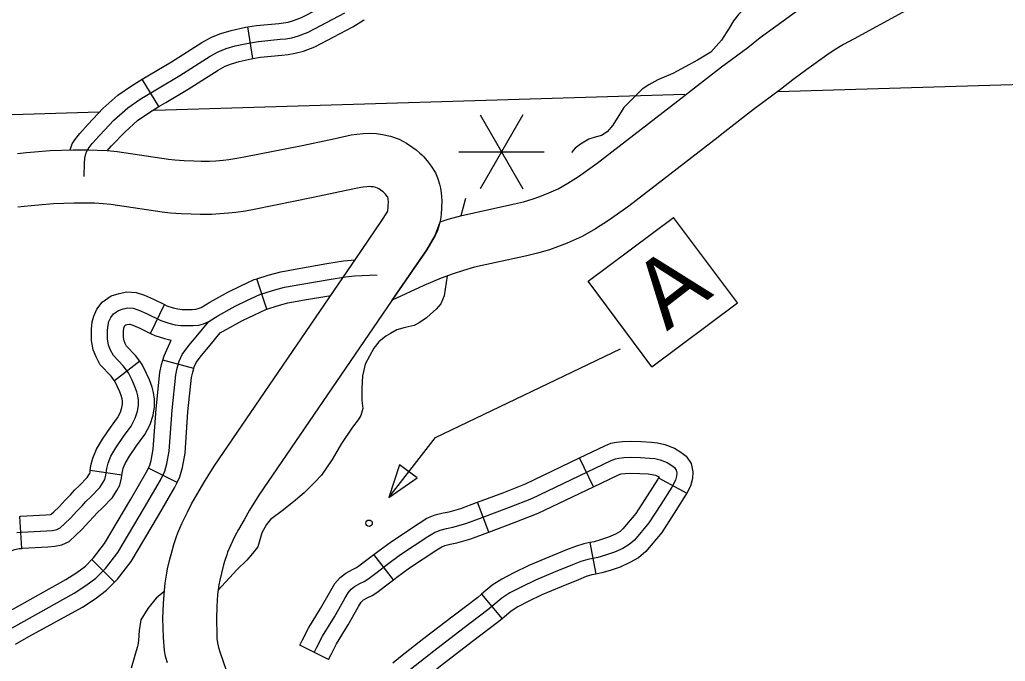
# Model space of a CAD drawing. Extents: x -3711 to 825, y -151 to 1050.
# Drawn here: x -2828.2 to -2776.5, y 291.3 to 325 of the extents above; entities that cross this region are included whole.
import ezdxf

# ---------------------------------------------------------------- set-up
doc = ezdxf.new("R2010")
doc.units = 0
for name, color, linetype in [('Level 10', 7, 'Continuous'), ('Level 32', 7, 'Continuous'), ('Level 35', 7, 'Continuous'), ('Level 48', 7, 'Continuous'), ('Level 5', 7, 'Continuous'), ('Level 57', 7, 'Continuous')]:
    doc.layers.add(name, color=color, linetype=linetype)

msp = doc.modelspace()

# ---------------------------------------------------------------- linework, layer by layer
at = {"layer": 'Level 10'}
for points in [[(-2781.289, 325.669), (-2784.41, 323.971), (-2784.959, 323.669), (-2785.452, 323.371), (-2785.849, 323.106), (-2786.891, 322.363), (-2787.635, 321.823), (-2788.274, 321.3), (-2789.685, 320.256), (-2791.36, 318.961), (-2791.549, 318.808), (-2796.241, 315.189), (-2797.309, 314.427), (-2797.995, 313.986), (-2798.695, 313.596), (-2799.472, 313.245), (-2799.985, 313.04), (-2800.41, 312.894), (-2801.033, 312.71), (-2801.598, 312.569), (-2804.337, 311.973), (-2804.917, 311.81), (-2805.469, 311.633), (-2806.101, 311.405), (-2807.006, 311.022), (-2808.664, 310.249)], [(-2808.664, 310.249), (-2806.854, 312.899), (-2806.413, 313.636), (-2806.15, 314.357), (-2805.725, 314.494), (-2805.014, 314.694), (-2802.236, 315.298), (-2801.77, 315.414), (-2801.262, 315.564), (-2800.962, 315.667), (-2800.569, 315.824), (-2799.956, 316.101), (-2799.436, 316.391), (-2798.88, 316.748), (-2797.911, 317.44), (-2793.288, 321.005), (-2793.101, 321.157), (-2791.376, 322.491), (-2789.996, 323.512), (-2789.347, 324.044), (-2788.528, 324.638), (-2787.441, 325.413)], [(-2828.337, 317.95), (-2827.872, 318.002), (-2827.449, 318.028), (-2826.627, 318.101), (-2825.41, 318.146), (-2824.849, 318.146), (-2824.588, 318.146), (-2824.163, 318.13), (-2823.634, 318.097), (-2823.108, 318.051), (-2820.405, 317.646), (-2820.085, 317.614), (-2819.587, 317.587), (-2819.083, 317.559), (-2818.695, 317.543), (-2818.251, 317.546), (-2817.922, 317.571), (-2817.533, 317.6), (-2817.237, 317.634), (-2816.831, 317.694), (-2816.447, 317.764), (-2813.387, 318.374), (-2811.668, 318.743), (-2810.816, 318.923), (-2810.531, 318.967), (-2810.197, 318.999), (-2809.862, 319.017), (-2809.498, 318.997), (-2809.167, 318.95), (-2808.747, 318.856), (-2808.308, 318.699), (-2807.923, 318.496), (-2807.59, 318.268), (-2807.413, 318.133), (-2807.209, 317.967), (-2807.114, 317.873), (-2807.019, 317.787), (-2806.828, 317.57), (-2806.615, 317.277), (-2806.391, 316.928), (-2806.287, 316.672), (-2806.228, 316.506), (-2806.181, 316.331), (-2806.135, 316.129), (-2806.092, 315.881), (-2806.064, 315.469), (-2806.072, 315.089), (-2806.089, 314.768), (-2806.133, 314.475), (-2806.194, 314.203), (-2806.288, 313.913), (-2806.413, 313.636), (-2806.529, 313.427), (-2806.854, 312.899)], [(-2809.205, 314.422), (-2808.95, 314.839), (-2808.919, 314.894), (-2808.906, 314.924), (-2808.9, 314.941), (-2808.889, 314.989), (-2808.88, 315.052), (-2808.872, 315.195), (-2808.868, 315.403), (-2808.877, 315.542), (-2808.884, 315.579), (-2808.899, 315.649), (-2808.93, 315.696), (-2809.016, 315.814), (-2809.044, 315.84), (-2809.087, 315.883), (-2809.145, 315.93), (-2809.232, 315.996), (-2809.374, 316.093), (-2809.44, 316.128), (-2809.526, 316.159), (-2809.67, 316.191), (-2809.775, 316.206), (-2809.863, 316.211), (-2809.989, 316.204), (-2810.183, 316.186), (-2810.311, 316.166), (-2811.085, 316.003), (-2812.819, 315.63), (-2815.921, 315.012), (-2816.376, 314.929), (-2816.87, 314.856), (-2817.265, 314.81), (-2817.714, 314.776), (-2818.139, 314.745), (-2818.743, 314.741), (-2819.218, 314.76), (-2819.741, 314.789), (-2820.299, 314.819), (-2820.751, 314.864), (-2823.438, 315.267), (-2823.844, 315.302), (-2824.303, 315.332), (-2824.64, 315.344), (-2824.849, 315.344), (-2825.358, 315.344), (-2826.452, 315.303), (-2827.239, 315.234), (-2827.63, 315.209), (-2827.994, 315.169), (-2828.332, 315.123)], [(-2820.465, 291.205), (-2820.545, 291.497), (-2820.583, 291.654), (-2820.62, 291.863), (-2820.646, 292.086), (-2820.662, 292.296), (-2820.679, 292.549), (-2820.703, 293.545), (-2820.672, 294.317), (-2820.628, 295.009), (-2820.592, 295.394), (-2820.526, 295.805), (-2820.457, 296.144), (-2820.358, 296.579), (-2820.224, 297.093), (-2820.129, 297.422), (-2820.006, 297.79), (-2819.921, 298.03), (-2819.816, 298.281), (-2819.698, 298.565), (-2819.422, 299.124), (-2819.197, 299.558), (-2818.874, 300.122), (-2818.561, 300.664), (-2818.012, 301.539), (-2810.765, 312.144), (-2810.617, 312.362), (-2809.205, 314.422)], [(-2806.854, 312.899), (-2808.302, 310.783), (-2808.45, 310.566), (-2815.668, 300.003), (-2816.16, 299.218), (-2816.445, 298.725), (-2816.736, 298.217), (-2816.921, 297.859), (-2817.146, 297.405), (-2817.229, 297.206), (-2817.306, 297.02), (-2817.357, 296.876), (-2817.453, 296.588), (-2817.522, 296.351), (-2817.635, 295.917), (-2817.718, 295.55), (-2817.769, 295.302), (-2817.811, 295.042), (-2817.834, 294.789), (-2817.874, 294.173), (-2817.899, 293.524), (-2817.879, 292.672), (-2817.867, 292.495), (-2817.857, 292.359), (-2817.847, 292.273), (-2817.838, 292.225), (-2817.83, 292.192), (-2817.782, 292.018), (-2817.708, 291.794), (-2817.211, 290.322)]]:
    msp.add_lwpolyline(points, dxfattribs=at)
at = {"layer": 'Level 32'}
for p, q in [((-2815.977, 322.934), (-2816.24, 324.595)), ((-2820.914, 320.41), (-2821.787, 321.846)), ((-2815.254, 309.772), (-2815.774, 311.371)), ((-2821.356, 308.507), (-2820.618, 310.017)), ((-2821.921, 307.046), (-2823.252, 306.019)), ((-2819.089, 306.653), (-2820.708, 307.106)), ((-2798.1, 300.451), (-2798.826, 301.968)), ((-2822.855, 301.062), (-2824.519, 301.3)), ((-2819.964, 300.67), (-2821.468, 301.421)), ((-2794.683, 300.913), (-2793.198, 300.125)), ((-2803.597, 298.075), (-2804.183, 299.651)), ((-2828.113, 297.22), (-2828.225, 298.898)), ((-2798.288, 297.52), (-2797.965, 295.87)), ((-2823.25, 295.442), (-2824.439, 296.631)), ((-2808.604, 295.57), (-2809.626, 296.905)), ((-2803.969, 294.817), (-2802.896, 293.523)), ((-2812.008, 291.384), (-2813.512, 292.135))]:
    msp.add_line(p, q, dxfattribs=at)
for points in [[(-2816.24, 324.595), (-2815.795, 324.665), (-2814.625, 324.779), (-2814.366, 324.804), (-2814.129, 324.847), (-2813.844, 324.924), (-2813.427, 325.086), (-2811.566, 326.058), (-2811.079, 326.353), (-2811.076, 326.355)], [(-2824.849, 316.745), (-2824.828, 317.443), (-2824.799, 317.705), (-2824.76, 317.937), (-2824.709, 318.072), (-2824.634, 318.189), (-2824.425, 318.468), (-2824.02, 318.915), (-2823.28, 319.697), (-2822.555, 320.339), (-2821.897, 320.795), (-2820.987, 321.349), (-2819.813, 322.038), (-2818.228, 323.049), (-2817.796, 323.286), (-2817.377, 323.454), (-2816.917, 323.594), (-2816.219, 323.747), (-2815.688, 323.831), (-2814.544, 323.943), (-2814.251, 323.971), (-2813.944, 324.026), (-2813.581, 324.124), (-2813.079, 324.32), (-2811.153, 325.325)], [(-2821.787, 321.846), (-2821.418, 322.07), (-2820.252, 322.755), (-2818.657, 323.772), (-2818.156, 324.048), (-2817.656, 324.248), (-2817.129, 324.407), (-2816.375, 324.574), (-2816.24, 324.595)], [(-2815.977, 322.934), (-2815.582, 322.997), (-2814.463, 323.106), (-2814.136, 323.137), (-2813.759, 323.206), (-2813.319, 323.324), (-2812.731, 323.553), (-2810.74, 324.592), (-2810.166, 324.94), (-2810.122, 324.971)], [(-2820.914, 320.41), (-2820.556, 320.627), (-2819.374, 321.321), (-2817.8, 322.325), (-2817.436, 322.525), (-2817.098, 322.66), (-2816.704, 322.78), (-2816.063, 322.921), (-2815.977, 322.934)], [(-2825.582, 318.14), (-2825.464, 318.451), (-2825.325, 318.668), (-2825.074, 319.003), (-2824.637, 319.486), (-2823.865, 320.302), (-2823.075, 321.002), (-2822.355, 321.501), (-2821.787, 321.846)], [(-2823.627, 318.096), (-2823.403, 318.344), (-2822.695, 319.092), (-2822.035, 319.677), (-2821.439, 320.09), (-2820.914, 320.41)], [(-2815.774, 311.371), (-2815.183, 311.563), (-2814.513, 311.744), (-2813.56, 311.917), (-2812.103, 312.169), (-2811.227, 312.306), (-2810.61, 312.37)], [(-2828.377, 298.045), (-2828.127, 298.062), (-2826.797, 298.145), (-2826.498, 298.162), (-2826.282, 298.212), (-2826.099, 298.295), (-2825.85, 298.528), (-2825.55, 298.81), (-2825.218, 299.177), (-2824.952, 299.459), (-2824.752, 299.676), (-2824.486, 299.925), (-2824.021, 300.408), (-2823.838, 300.691), (-2823.755, 300.84), (-2823.705, 301.057), (-2823.655, 301.406), (-2823.588, 301.689), (-2823.439, 302.055), (-2823.173, 302.504), (-2822.774, 303.087), (-2822.375, 303.636), (-2822.159, 304.052), (-2822.042, 304.418), (-2821.992, 304.717), (-2821.992, 305), (-2822.026, 305.233), (-2822.075, 305.433), (-2822.192, 305.749), (-2822.325, 306.048), (-2822.508, 306.431), (-2822.79, 306.797), (-2823.306, 307.346), (-2823.455, 307.629), (-2823.555, 307.878), (-2823.622, 308.211), (-2823.622, 308.444), (-2823.622, 308.677), (-2823.588, 308.943), (-2823.539, 309.126), (-2823.439, 309.343), (-2823.306, 309.526), (-2823.04, 309.709), (-2822.79, 309.792), (-2822.541, 309.842), (-2822.275, 309.825), (-2821.976, 309.725), (-2821.56, 309.542), (-2820.812, 309.176), (-2820.396, 309.043), (-2820.064, 308.96), (-2819.764, 308.927), (-2819.449, 308.91), (-2819.116, 308.91), (-2818.817, 308.943), (-2818.567, 309.01), (-2818.301, 309.126), (-2817.819, 309.426), (-2816.905, 309.925), (-2816.256, 310.241), (-2815.608, 310.541), (-2814.943, 310.757), (-2814.328, 310.923), (-2813.413, 311.09), (-2811.967, 311.339), (-2811.119, 311.472), (-2810.637, 311.522), (-2809.459, 311.573)], [(-2820.618, 310.017), (-2820.497, 309.958), (-2820.166, 309.852), (-2819.915, 309.789), (-2819.696, 309.765), (-2819.426, 309.751), (-2819.163, 309.751), (-2818.972, 309.772), (-2818.846, 309.806), (-2818.694, 309.872), (-2818.243, 310.152), (-2817.291, 310.672), (-2816.617, 311.001), (-2815.915, 311.325), (-2815.774, 311.371)], [(-2823.252, 306.019), (-2823.431, 306.251), (-2823.996, 306.853), (-2824.219, 307.275), (-2824.364, 307.638), (-2824.462, 308.128), (-2824.462, 308.444), (-2824.462, 308.729), (-2824.415, 309.107), (-2824.331, 309.415), (-2824.167, 309.77), (-2823.901, 310.136), (-2823.418, 310.468), (-2823.007, 310.606), (-2822.598, 310.688), (-2822.113, 310.657), (-2821.673, 310.51), (-2821.206, 310.305), (-2820.618, 310.017)], [(-2815.254, 309.772), (-2814.703, 309.951), (-2814.142, 310.103), (-2813.267, 310.262), (-2811.889, 310.5)], [(-2817.699, 308.534), (-2816.519, 309.178), (-2815.896, 309.482), (-2815.301, 309.757), (-2815.254, 309.772)], [(-2830.035, 292.254), (-2828.148, 293.318), (-2825.363, 294.861), (-2824.749, 295.266), (-2824.225, 295.655), (-2823.716, 296.165), (-2823.072, 297.004), (-2821.664, 299.372), (-2820.841, 300.795), (-2820.601, 301.275), (-2820.496, 301.65), (-2820.377, 302.324), (-2820.227, 304.467), (-2820.032, 306.325), (-2819.957, 306.67), (-2819.852, 307.044), (-2819.688, 307.404), (-2819.343, 307.869), (-2818.864, 308.423), (-2818.301, 309.126)], [(-2821.921, 307.046), (-2822.15, 307.343), (-2822.616, 307.839), (-2822.691, 307.982), (-2822.746, 308.119), (-2822.781, 308.294), (-2822.781, 308.444), (-2822.781, 308.625), (-2822.762, 308.78), (-2822.746, 308.838), (-2822.71, 308.915), (-2822.661, 308.949), (-2822.574, 308.978), (-2822.484, 308.996), (-2822.437, 308.993), (-2822.279, 308.94), (-2821.914, 308.78), (-2821.356, 308.507)], [(-2821.356, 308.507), (-2821.126, 308.394), (-2820.627, 308.234), (-2820.273, 308.146)], [(-2819.089, 306.653), (-2819.061, 306.754), (-2818.96, 306.974), (-2818.687, 307.343), (-2818.218, 307.885), (-2817.699, 308.534)], [(-2820.708, 307.106), (-2820.644, 307.334), (-2820.273, 308.146)], [(-2822.855, 301.062), (-2822.828, 301.25), (-2822.785, 301.432), (-2822.684, 301.68), (-2822.464, 302.052), (-2822.087, 302.602), (-2821.658, 303.192), (-2821.379, 303.728), (-2821.223, 304.22), (-2821.152, 304.648), (-2821.152, 305.06), (-2821.2, 305.395), (-2821.271, 305.68), (-2821.412, 306.065), (-2821.561, 306.4), (-2821.788, 306.874), (-2821.921, 307.046)], [(-2821.468, 301.421), (-2821.389, 301.579), (-2821.317, 301.837), (-2821.212, 302.427), (-2821.064, 304.54), (-2820.863, 306.459), (-2820.773, 306.872), (-2820.708, 307.106)], [(-2819.964, 300.67), (-2819.813, 300.971), (-2819.676, 301.462), (-2819.541, 302.221), (-2819.389, 304.394), (-2819.201, 306.192), (-2819.141, 306.467), (-2819.089, 306.653)], [(-2824.519, 301.3), (-2824.482, 301.562), (-2824.392, 301.946), (-2824.194, 302.43), (-2823.882, 302.956), (-2823.461, 303.571), (-2823.092, 304.079), (-2822.938, 304.375), (-2822.862, 304.615), (-2822.833, 304.787), (-2822.833, 304.94), (-2822.852, 305.071), (-2822.88, 305.185), (-2822.971, 305.433), (-2823.088, 305.696), (-2823.228, 305.988), (-2823.252, 306.019)], [(-2798.826, 301.968), (-2797.504, 302.6), (-2797.189, 302.733), (-2796.887, 302.793), (-2796.567, 302.821), (-2796.177, 302.847), (-2795.589, 302.837), (-2795.057, 302.799), (-2794.736, 302.757), (-2794.354, 302.677), (-2793.848, 302.472), (-2793.514, 302.265), (-2793.23, 302.052), (-2792.973, 301.666), (-2792.876, 301.243), (-2792.902, 300.878), (-2793.004, 300.489), (-2793.198, 300.125)], [(-2812.76, 291.759), (-2812.622, 292.036), (-2812.322, 292.613), (-2811.7, 293.629), (-2811.158, 294.586), (-2810.985, 294.886), (-2810.812, 295.083), (-2810.639, 295.221), (-2810.362, 295.371), (-2810.131, 295.486), (-2809.947, 295.602), (-2809.463, 295.971), (-2808.921, 296.387), (-2808.229, 296.894), (-2806.788, 297.84), (-2806.453, 298.06), (-2806.153, 298.175), (-2805.807, 298.256), (-2805.473, 298.325), (-2804.804, 298.521), (-2803.939, 298.844), (-2802.51, 299.375), (-2801.334, 299.837), (-2797.159, 301.833), (-2796.94, 301.925), (-2796.767, 301.96), (-2796.502, 301.983), (-2796.156, 302.006), (-2795.626, 301.997), (-2795.142, 301.962), (-2794.876, 301.928), (-2794.6, 301.87), (-2794.231, 301.72), (-2793.989, 301.57), (-2793.85, 301.466), (-2793.758, 301.328), (-2793.723, 301.178), (-2793.735, 301.016), (-2793.793, 300.797), (-2793.989, 300.427), (-2794.565, 299.516), (-2795.188, 298.558), (-2795.949, 297.647), (-2796.214, 297.416), (-2796.56, 297.22), (-2796.998, 297.023), (-2797.471, 296.862), (-2797.863, 296.747), (-2798.393, 296.643), (-2798.762, 296.527), (-2799.2, 296.354), (-2800.111, 295.985), (-2801.149, 295.546), (-2801.899, 295.189), (-2802.487, 294.877), (-2802.913, 294.6), (-2803.651, 293.989), (-2804.954, 292.996), (-2806.488, 291.819), (-2807.71, 290.862)], [(-2804.183, 299.651), (-2802.81, 300.16), (-2801.669, 300.608), (-2798.826, 301.968)], [(-2828.225, 298.898), (-2828.182, 298.901), (-2826.847, 298.984), (-2826.617, 298.997), (-2826.566, 299.009), (-2826.425, 299.14), (-2826.151, 299.399), (-2825.835, 299.747), (-2825.567, 300.032), (-2825.35, 300.268), (-2825.077, 300.524), (-2824.682, 300.933), (-2824.559, 301.123), (-2824.547, 301.145), (-2824.532, 301.211), (-2824.519, 301.3)], [(-2824.439, 296.631), (-2824.349, 296.72), (-2823.769, 297.476), (-2822.39, 299.797), (-2821.581, 301.194), (-2821.468, 301.421)], [(-2828.113, 297.22), (-2828.073, 297.223), (-2826.748, 297.306), (-2826.379, 297.326), (-2826.011, 297.411), (-2825.626, 297.587), (-2825.274, 297.915), (-2824.95, 298.222), (-2824.601, 298.606), (-2824.337, 298.886), (-2824.155, 299.083), (-2823.896, 299.327), (-2823.359, 299.883), (-2823.117, 300.258), (-2822.962, 300.536), (-2822.878, 300.903), (-2822.855, 301.062)], [(-2794.683, 300.913), (-2794.716, 300.85), (-2795.273, 299.97), (-2795.865, 299.058), (-2796.551, 298.237), (-2796.702, 298.105), (-2796.94, 297.971), (-2797.306, 297.806), (-2797.725, 297.663), (-2798.063, 297.564), (-2798.288, 297.52)], [(-2798.1, 300.451), (-2796.815, 301.066), (-2796.692, 301.118), (-2796.648, 301.126), (-2796.438, 301.145), (-2796.136, 301.165), (-2795.663, 301.157), (-2795.226, 301.125), (-2795.017, 301.098), (-2794.846, 301.062), (-2794.646, 300.981), (-2794.683, 300.913)], [(-2823.25, 295.442), (-2823.082, 295.61), (-2822.375, 296.532), (-2820.939, 298.946), (-2820.1, 300.397), (-2819.964, 300.67)], [(-2803.597, 298.075), (-2802.21, 298.59), (-2800.998, 299.065), (-2798.1, 300.451)], [(-2793.198, 300.125), (-2793.261, 300.005), (-2793.857, 299.062), (-2794.51, 298.058), (-2795.346, 297.056), (-2795.726, 296.726), (-2796.18, 296.469), (-2796.69, 296.24), (-2797.216, 296.061), (-2797.663, 295.929), (-2797.965, 295.87)], [(-2809.626, 296.905), (-2809.425, 297.059), (-2808.709, 297.585), (-2807.249, 298.543), (-2806.839, 298.812), (-2806.401, 298.98), (-2805.988, 299.077), (-2805.677, 299.141), (-2805.07, 299.319), (-2804.233, 299.632), (-2804.183, 299.651)], [(-2808.604, 295.57), (-2808.416, 295.714), (-2807.749, 296.204), (-2806.326, 297.138), (-2806.067, 297.307), (-2805.906, 297.37), (-2805.627, 297.435), (-2805.269, 297.509), (-2804.539, 297.723), (-2803.646, 298.057), (-2803.597, 298.075)], [(-2832.728, 294.703), (-2832.635, 294.792), (-2832.33, 295.021), (-2832.215, 295.115), (-2832.098, 295.17), (-2831.883, 295.246), (-2831.512, 295.347), (-2831.08, 295.506), (-2830.722, 295.73), (-2830.353, 295.989), (-2829.965, 296.293), (-2829.625, 296.54), (-2829.367, 296.712), (-2828.992, 296.922), (-2828.589, 297.131), (-2828.482, 297.164), (-2828.262, 297.21), (-2828.113, 297.22)], [(-2798.288, 297.52), (-2798.6, 297.459), (-2799.042, 297.32), (-2799.513, 297.135), (-2800.433, 296.762), (-2801.494, 296.313), (-2802.277, 295.94), (-2802.913, 295.603), (-2803.412, 295.279), (-2803.969, 294.817)], [(-2829.264, 293.654), (-2828.559, 294.051), (-2825.799, 295.581), (-2825.232, 295.955), (-2824.776, 296.293), (-2824.439, 296.631)], [(-2813.512, 292.135), (-2813.371, 292.418), (-2813.054, 293.027), (-2812.424, 294.056), (-2811.888, 295.003), (-2811.671, 295.379), (-2811.394, 295.693), (-2811.105, 295.924), (-2810.75, 296.117), (-2810.543, 296.22), (-2810.426, 296.294), (-2809.973, 296.639), (-2809.626, 296.905)], [(-2812.008, 291.384), (-2811.873, 291.655), (-2811.59, 292.199), (-2810.975, 293.202), (-2810.428, 294.17), (-2810.298, 294.394), (-2810.229, 294.472), (-2810.172, 294.518), (-2809.974, 294.626), (-2809.72, 294.753), (-2809.468, 294.91), (-2808.952, 295.303), (-2808.604, 295.57)], [(-2797.965, 295.87), (-2798.186, 295.827), (-2798.482, 295.734), (-2798.888, 295.574), (-2799.79, 295.208), (-2800.804, 294.78), (-2801.521, 294.438), (-2802.06, 294.152), (-2802.415, 293.922), (-2802.896, 293.523)], [(-2828.438, 292.189), (-2827.738, 292.584), (-2824.928, 294.141), (-2824.267, 294.577), (-2823.674, 295.017), (-2823.25, 295.442)], [(-2803.969, 294.817), (-2804.174, 294.647), (-2805.465, 293.664), (-2807.003, 292.484), (-2808.232, 291.521), (-2808.633, 291.199)], [(-2802.896, 293.523), (-2803.128, 293.33), (-2804.444, 292.329), (-2805.973, 291.155), (-2807.188, 290.203), (-2807.583, 289.887)]]:
    msp.add_lwpolyline(points, dxfattribs=at)
at = {"layer": 'Level 35'}
for points in [[(-2790.158, 325.575), (-2790.473, 325.238), (-2790.738, 324.913), (-2790.974, 324.53), (-2791.375, 323.903), (-2791.938, 323.274), (-2792.633, 322.843), (-2793.925, 322.147), (-2794.719, 321.816), (-2795.183, 321.551), (-2795.547, 321.319), (-2796.507, 320.358), (-2797.079, 319.438), (-2797.376, 319.084), (-2797.674, 318.898), (-2798.009, 318.805), (-2798.344, 318.693), (-2798.772, 318.433), (-2799.051, 318.228), (-2799.242, 318.008)], [(-2804.823, 315.577), (-2805.064, 314.682)], [(-2805.773, 311.524), (-2805.933, 310.482), (-2806.119, 310.054), (-2806.361, 309.775), (-2806.659, 309.514), (-2806.863, 309.328), (-2807.254, 309.067), (-2807.515, 308.918), (-2807.98, 308.806), (-2808.426, 308.695), (-2808.761, 308.49), (-2809.003, 308.36), (-2809.375, 308.062), (-2809.636, 307.726), (-2810.082, 306.888), (-2810.231, 306.274), (-2810.268, 305.604), (-2810.268, 304.989), (-2810.213, 304.561), (-2810.306, 304.188), (-2810.454, 303.965), (-2810.752, 303.574), (-2811.329, 302.717), (-2811.813, 301.879), (-2812.371, 301.06), (-2812.743, 300.669), (-2813.283, 300.129), (-2813.748, 299.757), (-2814.381, 299.235), (-2815.05, 298.732), (-2815.274, 298.472), (-2815.516, 298.043), (-2815.609, 297.671), (-2815.72, 297.299), (-2815.999, 296.945), (-2816.297, 296.591), (-2816.8, 296.107), (-2817.814, 295.003)], [(-2820.665, 294.931), (-2821.059, 294.608), (-2821.502, 294.062), (-2821.865, 293.472), (-2821.956, 292.916), (-2821.981, 292.381), (-2822.019, 292.133), (-2822.045, 292.07), (-2822.106, 291.845), (-2822.22, 291.473), (-2822.376, 290.926)]]:
    msp.add_lwpolyline(points, dxfattribs=at)
at = {"layer": 'Level 48'}
for p, q in [((-2801.809, 319.983), (-2804.05, 316.1)), ((-2804.05, 319.983), (-2801.809, 316.1)), ((-2805.171, 318.042), (-2800.688, 318.042))]:
    msp.add_line(p, q, dxfattribs=at)
at = {"layer": 'Level 5'}
for points in [[(-2729.532, 322.491), (-2775.536, 321.571), (-2788.411, 321.184)], [(-2793.293, 321.037), (-2821.147, 320.201)], [(-2824.058, 320.114), (-2833.198, 319.839), (-2834.582, 319.81)]]:
    msp.add_lwpolyline(points, dxfattribs=at)
at = {"layer": 'Level 57'}
for p, q in [((-2798.382, 311.24), (-2793.891, 314.593)), ((-2790.538, 310.102), (-2793.891, 314.593)), ((-2795.029, 306.749), (-2798.382, 311.24)), ((-2795.029, 306.749), (-2790.538, 310.102))]:
    msp.add_line(p, q, dxfattribs=at)
msp.add_lwpolyline([(-2808.842, 299.883), (-2806.399, 303.04), (-2796.679, 307.686)], dxfattribs=at)
msp.add_lwpolyline([(-2807.362, 300.922), (-2808.281, 301.602), (-2808.842, 299.883)], close=True, dxfattribs=at)
msp.add_circle((-2809.881, 298.539), 0.168, dxfattribs=at)

# ---------------------------------------------------------------- texts
msp.add_text('A', height=3.551, rotation=37.7481, dxfattribs=at).set_placement((-2794.242, 308.595))

doc.saveas('drawing.dxf')
